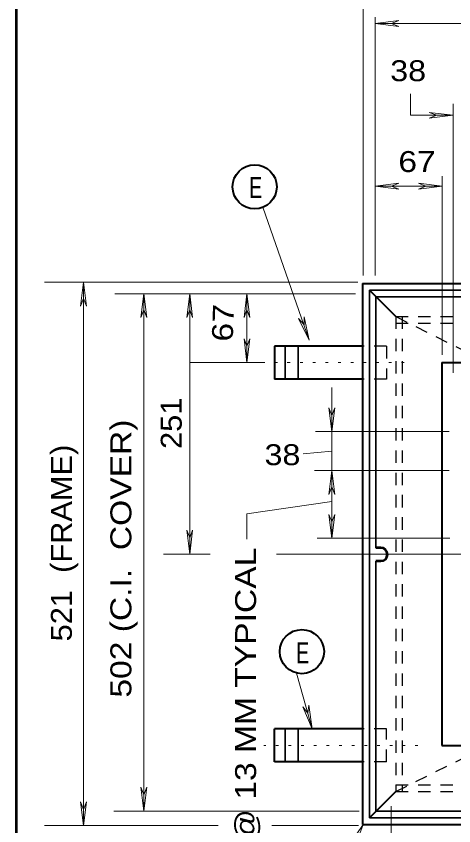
# Model space of a CAD drawing. Extents: x 312583 to 312854, y 144419 to 144597.
# Drawn here: x 312675.44 to 312691.31, y 144542.88 to 144572.27 of the extents above; entities that cross this region are included whole.
import ezdxf

# ---------------------------------------------------------------- set-up
doc = ezdxf.new("R2010")
doc.units = 0
doc.header["$LTSCALE"] = 0.3
doc.linetypes.add('DOTTED', pattern=[1.5, 0.3, -1.2])
doc.linetypes.add('SHORT_DASHED', pattern=[2.7, 1.5, -1.2])
doc.layers.add('1', color=7, linetype='Continuous', lineweight=40)
doc.layers.add('2', color=7, linetype='Continuous', lineweight=13)

msp = doc.modelspace()

# ---------------------------------------------------------------- linework, layer by layer
at = {"layer": '1', "lineweight": 53}
for p, q in [((312675.4374, 144585.0846), (312675.4374, 144521.3091)), ((312688.6605, 144552.9736), (312688.4842, 144552.9736)), ((312688.6605, 144552.4906), (312688.4842, 144552.4906))]:
    msp.add_line(p, q, dxfattribs=at)
at = {"layer": '1', "lineweight": 13}
msp.add_line((312689.7415, 144568.6749), (312689.7415, 144569.4493), dxfattribs=at)
at = {"layer": '1'}
for p, q in [((312688.0012, 144562.5723), (312688.0012, 144542.9226)), ((312688.2465, 144562.3269), (312689.2049, 144561.3686)), ((312684.8042, 144560.2953), (312684.8042, 144559.0916)), ((312687.9935, 144560.2953), (312684.8042, 144560.2953)), ((312690.8762, 144559.6973), (312722.0259, 144559.6973)), ((312690.8762, 144559.6973), (312690.8762, 144545.7976)), ((312687.9782, 144559.0916), (312684.8042, 144559.0916)), ((312684.8042, 144545.1996), (312684.8042, 144546.3956)), ((312688.0165, 144546.3956), (312684.8042, 144546.3956)), ((312690.8762, 144545.7976), (312722.0259, 144545.7976)), ((312688.0012, 144545.1996), (312684.8042, 144545.1996)), ((312689.2049, 144544.1186), (312688.2465, 144543.1603)), ((312688.0012, 144542.9226), (312724.9009, 144542.9226))]:
    msp.add_line(p, q, dxfattribs=at)
at = {"layer": '1', "lineweight": 35}
for p, q in [((312688.2465, 144562.3269), (312688.2465, 144543.1603)), ((312688.4842, 144562.0893), (312724.4179, 144562.0893)), ((312688.4842, 144562.0893), (312688.4842, 144552.9736)), ((312685.1875, 144560.2953), (312685.1875, 144559.0916)), ((312685.6705, 144560.2953), (312685.6705, 144559.0916)), ((312688.4842, 144552.4906), (312688.4842, 144543.4056)), ((312685.1875, 144546.3956), (312685.1875, 144545.1996)), ((312685.6705, 144546.3956), (312685.6705, 144545.1996)), ((312688.4842, 144543.4056), (312724.4179, 144543.4056)), ((312688.2465, 144543.1603), (312724.6632, 144543.1603))]:
    msp.add_line(p, q, dxfattribs=at)
at = {"layer": '1', "linetype": 'SHORT_DASHED', "lineweight": 25}
for p, q in [((312689.2049, 144544.1186), (312723.7049, 144561.3686)), ((312689.2049, 144561.3686), (312723.7049, 144544.1186)), ((312689.4425, 144561.3686), (312689.4425, 144544.1186)), ((312689.2049, 144561.1309), (312696.8869, 144561.1309)), ((312688.8675, 144560.2953), (312687.9935, 144560.2953)), ((312688.8675, 144560.2953), (312688.8675, 144559.0916)), ((312688.8675, 144559.0916), (312688.0012, 144559.0916)), ((312688.8675, 144546.3956), (312688.0165, 144546.3956)), ((312688.8675, 144545.1996), (312688.8675, 144546.3956)), ((312688.8675, 144545.1996), (312688.0012, 144545.1996)), ((312689.2049, 144544.3639), (312723.7049, 144544.3639))]:
    msp.add_line(p, q, dxfattribs=at)
at = {"layer": '1', "linetype": 'DOTTED', "lineweight": 13}
for p, q in [((312689.5115, 144559.6973), (312684.4209, 144559.6973)), ((312690.0099, 144545.7976), (312684.4209, 144545.7976))]:
    msp.add_line(p, q, dxfattribs=at)
at = {"layer": '1'}
msp.add_lwpolyline([(312688.0012, 144562.5723), (312724.9009, 144562.5723), (312724.9009, 144542.9226)], dxfattribs=at)
at = {"layer": '1', "lineweight": 35}
msp.add_lwpolyline([(312688.2465, 144562.3269), (312724.6632, 144562.3269), (312724.6632, 144543.1603)], dxfattribs=at)
at = {"layer": '1', "linetype": 'SHORT_DASHED', "lineweight": 25}
for points in [[(312689.2049, 144561.3686), (312689.2049, 144544.1186), (312723.7049, 144544.1186)], [(312689.2049, 144561.3686), (312698.9109, 144561.3686), (312723.7049, 144561.3686)]]:
    msp.add_lwpolyline(points, dxfattribs=at)
at = {"layer": '1', "lineweight": 53}
msp.add_arc((312688.6634, 144552.7321), 0.2396, 270, 90, dxfattribs=at)
at = {"layer": '2'}
for p, q in [((312688.0165, 144562.8636), (312688.0165, 144574.9386)), ((312688.4535, 144562.8636), (312688.4535, 144572.2399)), ((312688.4535, 144572.0099), (312689.3199, 144572.1173)), ((312689.3199, 144572.1173), (312689.0439, 144572.0099)), ((312688.4535, 144572.0099), (312724.4715, 144572.0099)), ((312688.4535, 144572.0099), (312689.3199, 144571.9026)), ((312689.3199, 144571.9026), (312689.0439, 144572.0099)), ((312691.2825, 144559.3216), (312691.2825, 144569.0889)), ((312689.7415, 144568.6749), (312691.2825, 144568.6749)), ((312690.4162, 144568.7823), (312690.6922, 144568.6749)), ((312691.2825, 144568.6749), (312690.4162, 144568.7823)), ((312690.4162, 144568.5676), (312690.6922, 144568.6749)), ((312691.2825, 144568.6749), (312690.4162, 144568.5676)), ((312690.8915, 144559.9809), (312690.8915, 144566.4593)), ((312688.4535, 144566.0989), (312689.3199, 144566.2063)), ((312689.3199, 144566.2063), (312689.0439, 144566.0989)), ((312690.0252, 144566.2063), (312690.3012, 144566.0989)), ((312690.8915, 144566.0989), (312690.0252, 144566.2063)), ((312688.4535, 144566.0989), (312690.8915, 144566.0989)), ((312688.4535, 144566.0989), (312689.3199, 144565.9916)), ((312689.3199, 144565.9916), (312689.0439, 144566.0989)), ((312690.0252, 144565.9916), (312690.3012, 144566.0989)), ((312690.8915, 144566.0989), (312690.0252, 144565.9916)), ((312684.3825, 144565.3399), (312686.0692, 144560.5099)), ((312687.8249, 144562.6106), (312676.4615, 144562.6106)), ((312677.8749, 144562.6106), (312677.7676, 144561.7443)), ((312677.8749, 144542.8843), (312677.8749, 144562.6106)), ((312677.8749, 144562.6106), (312677.9823, 144561.7443)), ((312687.7405, 144562.1966), (312679.0128, 144562.1966)), ((312680.0672, 144562.1966), (312679.9598, 144561.3303)), ((312680.0672, 144543.4133), (312680.0672, 144562.1966)), ((312680.0672, 144562.1966), (312680.1745, 144561.3303)), ((312681.7293, 144562.1966), (312681.6219, 144561.3303)), ((312681.7293, 144552.7436), (312681.7293, 144562.1966)), ((312681.7293, 144562.1966), (312681.8366, 144561.3303)), ((312683.8075, 144562.1966), (312683.7002, 144561.3303)), ((312683.8075, 144559.6973), (312683.8075, 144562.1966)), ((312683.8075, 144562.1966), (312683.9149, 144561.3303)), ((312677.7676, 144561.7443), (312677.8749, 144562.0203)), ((312677.9823, 144561.7443), (312677.8749, 144562.0203)), ((312679.9598, 144561.3303), (312680.0672, 144561.6063)), ((312680.1745, 144561.3303), (312680.0672, 144561.6063)), ((312681.6219, 144561.3303), (312681.7293, 144561.6063)), ((312681.8366, 144561.3303), (312681.7293, 144561.6063)), ((312683.7002, 144561.3303), (312683.8075, 144561.6063)), ((312683.9149, 144561.3303), (312683.8075, 144561.6063)), ((312685.6782, 144561.2919), (312685.8775, 144561.0619)), ((312686.0692, 144560.5099), (312685.6782, 144561.2919)), ((312685.8852, 144561.3609), (312685.8775, 144561.0619)), ((312686.0692, 144560.5099), (312685.8852, 144561.3609)), ((312683.7002, 144560.5636), (312683.8075, 144560.2876)), ((312683.8075, 144559.6973), (312683.7002, 144560.5636)), ((312683.9149, 144560.5636), (312683.8075, 144560.2876)), ((312683.8075, 144559.6973), (312683.9149, 144560.5636)), ((312684.4209, 144559.6973), (312681.7529, 144559.6973)), ((312686.7745, 144558.0566), (312686.8819, 144557.7806)), ((312686.8819, 144557.1903), (312686.7745, 144558.0566)), ((312686.9892, 144558.0566), (312686.8819, 144557.7806)), ((312686.8819, 144557.1903), (312686.9892, 144558.0566)), ((312691.1445, 144557.1903), (312686.2992, 144557.1903)), ((312685.8469, 144556.3853), (312686.8819, 144556.4773)), ((312691.1445, 144555.7796), (312686.2532, 144555.7796)), ((312686.8819, 144555.7719), (312686.7745, 144554.9056)), ((312686.8819, 144553.3186), (312686.8819, 144555.7719)), ((312686.8819, 144555.7719), (312686.9892, 144554.9056)), ((312686.7745, 144554.9056), (312686.8819, 144555.1816)), ((312686.9892, 144554.9056), (312686.8819, 144555.1816)), ((312686.7745, 144554.1849), (312686.8819, 144553.9089)), ((312686.8819, 144553.3186), (312686.7745, 144554.1849)), ((312686.9892, 144554.1849), (312686.8819, 144553.9089)), ((312686.8819, 144553.3186), (312686.9892, 144554.1849)), ((312681.6219, 144553.6099), (312681.7293, 144553.3339)), ((312681.7293, 144552.7436), (312681.6219, 144553.6099)), ((312681.8366, 144553.6099), (312681.7293, 144553.3339)), ((312681.7293, 144552.7436), (312681.8366, 144553.6099)), ((312691.1675, 144553.3186), (312686.3529, 144553.3186)), ((312682.4735, 144552.7436), (312680.7841, 144552.7436)), ((312692.5552, 144552.7436), (312684.8809, 144552.7436)), ((312685.6092, 144548.4196), (312686.1765, 144546.3956)), ((312685.8392, 144547.2006), (312686.0155, 144546.9629)), ((312686.1765, 144546.3956), (312685.8392, 144547.2006)), ((312686.0462, 144547.2619), (312686.0155, 144546.9629)), ((312686.1765, 144546.3956), (312686.0462, 144547.2619)), ((312679.9598, 144544.2796), (312680.0672, 144544.0036)), ((312680.0672, 144543.4133), (312679.9598, 144544.2796)), ((312680.1745, 144544.2796), (312680.0672, 144544.0036)), ((312680.0672, 144543.4133), (312680.1745, 144544.2796)), ((312677.7676, 144543.7506), (312677.8749, 144543.4746)), ((312677.8749, 144542.8843), (312677.7676, 144543.7506)), ((312677.9823, 144543.7506), (312677.8749, 144543.4746)), ((312677.8749, 144542.8843), (312677.9823, 144543.7506)), ((312689.0362, 144543.5896), (312689.0362, 144540.4079)), ((312687.8785, 144543.4133), (312678.9774, 144543.4133)), ((312682.7649, 144542.8843), (312676.4615, 144542.8843)), ((312687.8479, 144542.8843), (312684.7122, 144542.8843)), ((312688.0242, 144542.9226), (312687.5259, 144542.2019)), ((312688.0242, 144542.9226), (312687.7175, 144542.1023))]:
    msp.add_line(p, q, dxfattribs=at)
for points in [[(312686.8819, 144555.7719), (312686.8819, 144557.1903), (312686.8819, 144558.7926)], [(312683.7999, 144553.2879), (312683.7999, 144554.2003), (312686.8819, 144554.6526)]]:
    msp.add_lwpolyline(points, dxfattribs=at)
at = {"layer": '2', "lineweight": 40}
for centre in [(312684.0864, 144566.0807), (312685.8009, 144549.2006)]:
    msp.add_circle(centre, 0.8012, dxfattribs=at)

# ---------------------------------------------------------------- texts
at = {"layer": '2'}
for s, width, p in [('38 ', 1.15, (312689.0036, 144569.914)), ('67 ', 1.2, (312689.2981, 144566.6154)), ('E', 0.7, (312683.8889, 144565.6763)), ('38 ', 1.15, (312684.4446, 144555.9713)), ('E', 0.7, (312685.5928, 144548.778))]:
    msp.add_text(s, height=0.76, dxfattribs=dict(at, width=width)).set_placement(p)
for s, rotation, width, p in [('67 ', 87.879, 1.2, (312683.289, 144560.4477)), ('251 ', 90, 1.1, (312681.441, 144556.5588)), ('502 (C.I.  COVER)', 90, 1.2, (312679.6138, 144547.5304)), ('521  (FRAME)', 90, 1.1, (312677.4563, 144549.5726)), ('5 @ 13 MM TYPICAL', 90, 1.2, (312684.1385, 144541.2314))]:
    msp.add_text(s, height=0.76, rotation=rotation, dxfattribs=dict(at, width=width)).set_placement(p)

doc.saveas('drawing.dxf')
